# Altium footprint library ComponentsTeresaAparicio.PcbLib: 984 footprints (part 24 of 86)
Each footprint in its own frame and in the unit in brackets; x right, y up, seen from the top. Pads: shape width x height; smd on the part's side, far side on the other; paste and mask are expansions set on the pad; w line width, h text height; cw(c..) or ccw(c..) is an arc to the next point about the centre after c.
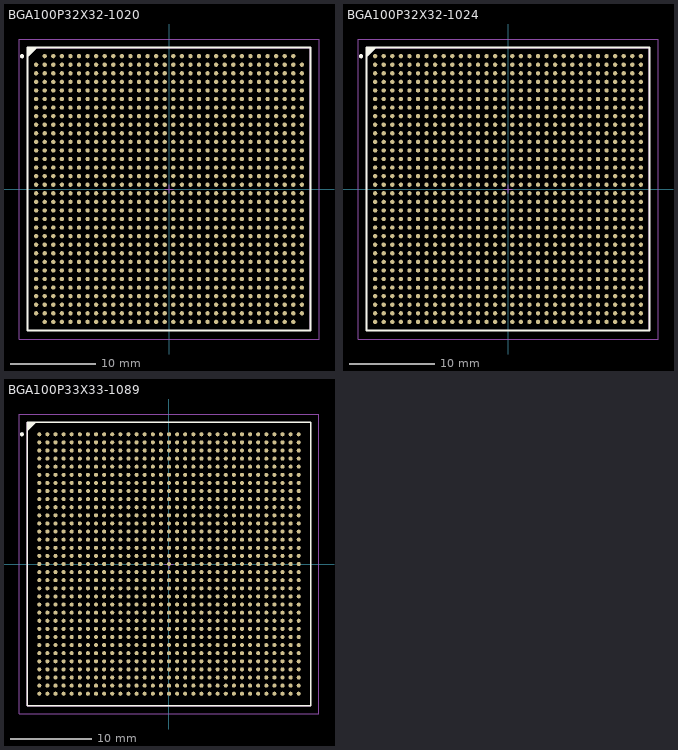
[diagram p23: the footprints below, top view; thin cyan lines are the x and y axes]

## BGA100P32X32-1020 [mm] "BGA, 1020-Leads, Body 33x33mm, Pitch 1mm"
height 3.5
pads (1020):
  round 0.5 smd: A2(-14.5,15.5) A3(-13.5,15.5) A4(-12.5,15.5) A5(-11.5,15.5) A6(-10.5,15.5) A7(-9.5,15.5) A8(-8.5,15.5) A9(-7.5,15.5) A10(-6.5,15.5) A11(-5.5,15.5) A12(-4.5,15.5) A13(-3.5,15.5) A14(-2.5,15.5) A15(-1.5,15.5) A16(-0.5,15.5) A17(0.5,15.5) A18(1.5,15.5) A19(2.5,15.5) A20(3.5,15.5) A21(4.5,15.5) A22(5.5,15.5) A23(6.5,15.5) A24(7.5,15.5) A25(8.5,15.5) A26(9.5,15.5) A27(10.5,15.5) A28(11.5,15.5) A29(12.5,15.5) A30(13.5,15.5) A31(14.5,15.5) AA1(-15.5,-4.5) AA2(-14.5,-4.5) AA3(-13.5,-4.5) AA4(-12.5,-4.5) AA5(-11.5,-4.5) AA6(-10.5,-4.5) AA7(-9.5,-4.5) AA8(-8.5,-4.5) AA9(-7.5,-4.5) AA10(-6.5,-4.5) AA11(-5.5,-4.5) AA12(-4.5,-4.5) AA13(-3.5,-4.5) AA14(-2.5,-4.5) AA15(-1.5,-4.5) AA16(-0.5,-4.5) AA17(0.5,-4.5) AA18(1.5,-4.5) AA19(2.5,-4.5) AA20(3.5,-4.5) AA21(4.5,-4.5) AA22(5.5,-4.5) AA23(6.5,-4.5) AA24(7.5,-4.5) AA25(8.5,-4.5) AA26(9.5,-4.5) AA27(10.5,-4.5) AA28(11.5,-4.5) AA29(12.5,-4.5) AA30(13.5,-4.5) AA31(14.5,-4.5) AA32(15.5,-4.5) AB1(-15.5,-5.5) AB2(-14.5,-5.5) AB3(-13.5,-5.5) AB4(-12.5,-5.5) AB5(-11.5,-5.5) AB6(-10.5,-5.5) AB7(-9.5,-5.5) AB8(-8.5,-5.5) AB9(-7.5,-5.5) AB10(-6.5,-5.5) AB11(-5.5,-5.5) AB12(-4.5,-5.5) AB13(-3.5,-5.5) AB14(-2.5,-5.5) AB15(-1.5,-5.5) AB16(-0.5,-5.5) AB17(0.5,-5.5) AB18(1.5,-5.5) AB19(2.5,-5.5) AB20(3.5,-5.5) AB21(4.5,-5.5) AB22(5.5,-5.5) AB23(6.5,-5.5) AB24(7.5,-5.5) AB25(8.5,-5.5) AB26(9.5,-5.5) AB27(10.5,-5.5) AB28(11.5,-5.5) AB29(12.5,-5.5) AB30(13.5,-5.5) AB31(14.5,-5.5) AB32(15.5,-5.5) AC1(-15.5,-6.5) AC2(-14.5,-6.5) AC3(-13.5,-6.5) AC4(-12.5,-6.5) AC5(-11.5,-6.5) AC6(-10.5,-6.5) AC7(-9.5,-6.5) AC8(-8.5,-6.5) AC9(-7.5,-6.5) AC10(-6.5,-6.5) AC11(-5.5,-6.5) AC12(-4.5,-6.5) AC13(-3.5,-6.5) AC14(-2.5,-6.5) AC15(-1.5,-6.5) AC16(-0.5,-6.5) AC17(0.5,-6.5) AC18(1.5,-6.5) AC19(2.5,-6.5) AC20(3.5,-6.5) AC21(4.5,-6.5) AC22(5.5,-6.5) AC23(6.5,-6.5) AC24(7.5,-6.5) AC25(8.5,-6.5) AC26(9.5,-6.5) AC27(10.5,-6.5) AC28(11.5,-6.5) AC29(12.5,-6.5) AC30(13.5,-6.5) AC31(14.5,-6.5) AC32(15.5,-6.5) AD1(-15.5,-7.5) AD2(-14.5,-7.5) AD3(-13.5,-7.5) AD4(-12.5,-7.5) AD5(-11.5,-7.5) AD6(-10.5,-7.5) AD7(-9.5,-7.5) AD8(-8.5,-7.5) AD9(-7.5,-7.5) AD10(-6.5,-7.5) AD11(-5.5,-7.5) AD12(-4.5,-7.5) AD13(-3.5,-7.5) AD14(-2.5,-7.5) AD15(-1.5,-7.5) AD16(-0.5,-7.5) AD17(0.5,-7.5) AD18(1.5,-7.5) AD19(2.5,-7.5) AD20(3.5,-7.5) AD21(4.5,-7.5) AD22(5.5,-7.5) AD23(6.5,-7.5) AD24(7.5,-7.5) AD25(8.5,-7.5) AD26(9.5,-7.5) AD27(10.5,-7.5) AD28(11.5,-7.5) AD29(12.5,-7.5) AD30(13.5,-7.5) AD31(14.5,-7.5) AD32(15.5,-7.5) AE1(-15.5,-8.5) AE2(-14.5,-8.5) AE3(-13.5,-8.5) AE4(-12.5,-8.5) AE5(-11.5,-8.5) AE6(-10.5,-8.5) AE7(-9.5,-8.5) AE8(-8.5,-8.5) AE9(-7.5,-8.5) AE10(-6.5,-8.5) AE11(-5.5,-8.5) AE12(-4.5,-8.5) AE13(-3.5,-8.5) AE14(-2.5,-8.5) AE15(-1.5,-8.5) AE16(-0.5,-8.5) AE17(0.5,-8.5) AE18(1.5,-8.5) AE19(2.5,-8.5) AE20(3.5,-8.5) AE21(4.5,-8.5) AE22(5.5,-8.5) AE23(6.5,-8.5) AE24(7.5,-8.5) AE25(8.5,-8.5) AE26(9.5,-8.5) AE27(10.5,-8.5) AE28(11.5,-8.5) AE29(12.5,-8.5) AE30(13.5,-8.5) AE31(14.5,-8.5) AE32(15.5,-8.5) AF1(-15.5,-9.5) AF2(-14.5,-9.5) AF3(-13.5,-9.5) AF4(-12.5,-9.5) AF5(-11.5,-9.5) AF6(-10.5,-9.5) AF7(-9.5,-9.5) AF8(-8.5,-9.5) AF9(-7.5,-9.5) AF10(-6.5,-9.5) AF11(-5.5,-9.5) AF12(-4.5,-9.5) AF13(-3.5,-9.5) AF14(-2.5,-9.5) AF15(-1.5,-9.5) AF16(-0.5,-9.5) AF17(0.5,-9.5) AF18(1.5,-9.5) AF19(2.5,-9.5) AF20(3.5,-9.5) AF21(4.5,-9.5) AF22(5.5,-9.5) AF23(6.5,-9.5) AF24(7.5,-9.5) AF25(8.5,-9.5) AF26(9.5,-9.5) AF27(10.5,-9.5) AF28(11.5,-9.5) AF29(12.5,-9.5) AF30(13.5,-9.5) AF31(14.5,-9.5) AF32(15.5,-9.5) AG1(-15.5,-10.5) AG2(-14.5,-10.5) AG3(-13.5,-10.5) AG4(-12.5,-10.5) AG5(-11.5,-10.5) AG6(-10.5,-10.5) AG7(-9.5,-10.5) AG8(-8.5,-10.5) AG9(-7.5,-10.5) AG10(-6.5,-10.5) AG11(-5.5,-10.5) AG12(-4.5,-10.5) AG13(-3.5,-10.5) AG14(-2.5,-10.5) AG15(-1.5,-10.5) AG16(-0.5,-10.5) AG17(0.5,-10.5) AG18(1.5,-10.5) AG19(2.5,-10.5) AG20(3.5,-10.5) AG21(4.5,-10.5) AG22(5.5,-10.5) AG23(6.5,-10.5) AG24(7.5,-10.5) AG25(8.5,-10.5) AG26(9.5,-10.5) AG27(10.5,-10.5) AG28(11.5,-10.5) AG29(12.5,-10.5) AG30(13.5,-10.5) AG31(14.5,-10.5) AG32(15.5,-10.5) AH1(-15.5,-11.5) AH2(-14.5,-11.5) AH3(-13.5,-11.5) AH4(-12.5,-11.5) AH5(-11.5,-11.5) AH6(-10.5,-11.5) AH7(-9.5,-11.5) AH8(-8.5,-11.5) AH9(-7.5,-11.5) AH10(-6.5,-11.5) AH11(-5.5,-11.5) AH12(-4.5,-11.5) AH13(-3.5,-11.5) AH14(-2.5,-11.5) AH15(-1.5,-11.5) AH16(-0.5,-11.5) AH17(0.5,-11.5) AH18(1.5,-11.5) AH19(2.5,-11.5) AH20(3.5,-11.5) AH21(4.5,-11.5) AH22(5.5,-11.5) AH23(6.5,-11.5) AH24(7.5,-11.5) AH25(8.5,-11.5) AH26(9.5,-11.5) AH27(10.5,-11.5) AH28(11.5,-11.5) AH29(12.5,-11.5) AH30(13.5,-11.5) AH31(14.5,-11.5) AH32(15.5,-11.5) AJ1(-15.5,-12.5) AJ2(-14.5,-12.5) AJ3(-13.5,-12.5) AJ4(-12.5,-12.5) AJ5(-11.5,-12.5) AJ6(-10.5,-12.5) AJ7(-9.5,-12.5) AJ8(-8.5,-12.5) AJ9(-7.5,-12.5) AJ10(-6.5,-12.5) AJ11(-5.5,-12.5) AJ12(-4.5,-12.5) AJ13(-3.5,-12.5) AJ14(-2.5,-12.5) AJ15(-1.5,-12.5) AJ16(-0.5,-12.5) AJ17(0.5,-12.5) AJ18(1.5,-12.5) AJ19(2.5,-12.5) AJ20(3.5,-12.5) AJ21(4.5,-12.5) AJ22(5.5,-12.5) AJ23(6.5,-12.5) AJ24(7.5,-12.5) AJ25(8.5,-12.5) AJ26(9.5,-12.5) AJ27(10.5,-12.5) AJ28(11.5,-12.5) AJ29(12.5,-12.5) AJ30(13.5,-12.5) AJ31(14.5,-12.5) AJ32(15.5,-12.5) AK1(-15.5,-13.5) AK2(-14.5,-13.5) AK3(-13.5,-13.5) AK4(-12.5,-13.5) AK5(-11.5,-13.5) AK6(-10.5,-13.5) AK7(-9.5,-13.5) AK8(-8.5,-13.5) AK9(-7.5,-13.5) AK10(-6.5,-13.5) AK11(-5.5,-13.5) AK12(-4.5,-13.5) AK13(-3.5,-13.5) AK14(-2.5,-13.5) AK15(-1.5,-13.5) AK16(-0.5,-13.5) AK17(0.5,-13.5) AK18(1.5,-13.5) AK19(2.5,-13.5) AK20(3.5,-13.5) AK21(4.5,-13.5) AK22(5.5,-13.5) AK23(6.5,-13.5) AK24(7.5,-13.5) AK25(8.5,-13.5) AK26(9.5,-13.5) AK27(10.5,-13.5) AK28(11.5,-13.5) AK29(12.5,-13.5) AK30(13.5,-13.5) AK31(14.5,-13.5) AK32(15.5,-13.5) AL1(-15.5,-14.5) AL2(-14.5,-14.5) AL3(-13.5,-14.5) AL4(-12.5,-14.5) AL5(-11.5,-14.5) AL6(-10.5,-14.5) AL7(-9.5,-14.5) AL8(-8.5,-14.5) AL9(-7.5,-14.5) AL10(-6.5,-14.5) AL11(-5.5,-14.5) AL12(-4.5,-14.5) AL13(-3.5,-14.5) AL14(-2.5,-14.5) AL15(-1.5,-14.5) AL16(-0.5,-14.5) AL17(0.5,-14.5) AL18(1.5,-14.5) AL19(2.5,-14.5) AL20(3.5,-14.5) AL21(4.5,-14.5) AL22(5.5,-14.5) AL23(6.5,-14.5) AL24(7.5,-14.5) AL25(8.5,-14.5) AL26(9.5,-14.5) AL27(10.5,-14.5) AL28(11.5,-14.5) AL29(12.5,-14.5) AL30(13.5,-14.5) AL31(14.5,-14.5) AL32(15.5,-14.5) AM2(-14.5,-15.5) AM3(-13.5,-15.5) AM4(-12.5,-15.5) AM5(-11.5,-15.5) AM6(-10.5,-15.5) AM7(-9.5,-15.5) AM8(-8.5,-15.5) AM9(-7.5,-15.5) AM10(-6.5,-15.5) AM11(-5.5,-15.5) AM12(-4.5,-15.5) AM13(-3.5,-15.5) AM14(-2.5,-15.5) AM15(-1.5,-15.5) AM16(-0.5,-15.5) AM17(0.5,-15.5) AM18(1.5,-15.5) AM19(2.5,-15.5) AM20(3.5,-15.5) AM21(4.5,-15.5) AM22(5.5,-15.5) AM23(6.5,-15.5) AM24(7.5,-15.5) AM25(8.5,-15.5) AM26(9.5,-15.5) AM27(10.5,-15.5) AM28(11.5,-15.5) AM29(12.5,-15.5) AM30(13.5,-15.5) AM31(14.5,-15.5) B1(-15.5,14.5) B2(-14.5,14.5) B3(-13.5,14.5) B4(-12.5,14.5) B5(-11.5,14.5) B6(-10.5,14.5) B7(-9.5,14.5) B8(-8.5,14.5) B9(-7.5,14.5) B10(-6.5,14.5) B11(-5.5,14.5) B12(-4.5,14.5) B13(-3.5,14.5) B14(-2.5,14.5) B15(-1.5,14.5) B16(-0.5,14.5) B17(0.5,14.5) B18(1.5,14.5) B19(2.5,14.5) B20(3.5,14.5) B21(4.5,14.5) B22(5.5,14.5) B23(6.5,14.5) B24(7.5,14.5) B25(8.5,14.5) B26(9.5,14.5) B27(10.5,14.5) B28(11.5,14.5) B29(12.5,14.5) B30(13.5,14.5) B31(14.5,14.5) B32(15.5,14.5) C1(-15.5,13.5) C2(-14.5,13.5) C3(-13.5,13.5) C4(-12.5,13.5) C5(-11.5,13.5) C6(-10.5,13.5) C7(-9.5,13.5) C8(-8.5,13.5) C9(-7.5,13.5) C10(-6.5,13.5) C11(-5.5,13.5) C12(-4.5,13.5) C13(-3.5,13.5) C14(-2.5,13.5) C15(-1.5,13.5) C16(-0.5,13.5) C17(0.5,13.5) C18(1.5,13.5) C19(2.5,13.5) C20(3.5,13.5) C21(4.5,13.5) C22(5.5,13.5) C23(6.5,13.5) C24(7.5,13.5) C25(8.5,13.5) C26(9.5,13.5) C27(10.5,13.5) C28(11.5,13.5) C29(12.5,13.5) C30(13.5,13.5) C31(14.5,13.5) C32(15.5,13.5) D1(-15.5,12.5) D2(-14.5,12.5) D3(-13.5,12.5) D4(-12.5,12.5) D5(-11.5,12.5) D6(-10.5,12.5) D7(-9.5,12.5) D8(-8.5,12.5) D9(-7.5,12.5) D10(-6.5,12.5) D11(-5.5,12.5) D12(-4.5,12.5) D13(-3.5,12.5) D14(-2.5,12.5) D15(-1.5,12.5) D16(-0.5,12.5) D17(0.5,12.5) D18(1.5,12.5) D19(2.5,12.5) D20(3.5,12.5) D21(4.5,12.5) D22(5.5,12.5) D23(6.5,12.5) D24(7.5,12.5) D25(8.5,12.5) D26(9.5,12.5) D27(10.5,12.5) D28(11.5,12.5) D29(12.5,12.5) D30(13.5,12.5) D31(14.5,12.5) D32(15.5,12.5) E1(-15.5,11.5) E2(-14.5,11.5) E3(-13.5,11.5) E4(-12.5,11.5) E5(-11.5,11.5) E6(-10.5,11.5) E7(-9.5,11.5) E8(-8.5,11.5) E9(-7.5,11.5) E10(-6.5,11.5) E11(-5.5,11.5) E12(-4.5,11.5) E13(-3.5,11.5) E14(-2.5,11.5) E15(-1.5,11.5) E16(-0.5,11.5) E17(0.5,11.5) E18(1.5,11.5) E19(2.5,11.5) E20(3.5,11.5) E21(4.5,11.5) E22(5.5,11.5) E23(6.5,11.5) E24(7.5,11.5) E25(8.5,11.5) E26(9.5,11.5) E27(10.5,11.5) E28(11.5,11.5) E29(12.5,11.5) E30(13.5,11.5) E31(14.5,11.5) E32(15.5,11.5) F1(-15.5,10.5) F2(-14.5,10.5) F3(-13.5,10.5) F4(-12.5,10.5) F5(-11.5,10.5) F6(-10.5,10.5) F7(-9.5,10.5) F8(-8.5,10.5) F9(-7.5,10.5) F10(-6.5,10.5) F11(-5.5,10.5) F12(-4.5,10.5) F13(-3.5,10.5) F14(-2.5,10.5) F15(-1.5,10.5) F16(-0.5,10.5) F17(0.5,10.5) F18(1.5,10.5) F19(2.5,10.5) F20(3.5,10.5) F21(4.5,10.5) F22(5.5,10.5) F23(6.5,10.5) F24(7.5,10.5) F25(8.5,10.5) F26(9.5,10.5) F27(10.5,10.5) F28(11.5,10.5) F29(12.5,10.5) F30(13.5,10.5) F31(14.5,10.5) F32(15.5,10.5) G1(-15.5,9.5) G2(-14.5,9.5) G3(-13.5,9.5) G4(-12.5,9.5) G5(-11.5,9.5) G6(-10.5,9.5) G7(-9.5,9.5) G8(-8.5,9.5) G9(-7.5,9.5) G10(-6.5,9.5) G11(-5.5,9.5) G12(-4.5,9.5) G13(-3.5,9.5) G14(-2.5,9.5) G15(-1.5,9.5) G16(-0.5,9.5) G17(0.5,9.5) G18(1.5,9.5) G19(2.5,9.5) G20(3.5,9.5) G21(4.5,9.5) G22(5.5,9.5) G23(6.5,9.5) G24(7.5,9.5) G25(8.5,9.5) G26(9.5,9.5) G27(10.5,9.5) G28(11.5,9.5) G29(12.5,9.5) G30(13.5,9.5) G31(14.5,9.5) G32(15.5,9.5) H1(-15.5,8.5) H2(-14.5,8.5) H3(-13.5,8.5) H4(-12.5,8.5) H5(-11.5,8.5) H6(-10.5,8.5) H7(-9.5,8.5) H8(-8.5,8.5) H9(-7.5,8.5) H10(-6.5,8.5) H11(-5.5,8.5) H12(-4.5,8.5) H13(-3.5,8.5) H14(-2.5,8.5) H15(-1.5,8.5) H16(-0.5,8.5) H17(0.5,8.5) H18(1.5,8.5) H19(2.5,8.5) H20(3.5,8.5) H21(4.5,8.5) H22(5.5,8.5) H23(6.5,8.5) H24(7.5,8.5) H25(8.5,8.5) H26(9.5,8.5) H27(10.5,8.5) H28(11.5,8.5) H29(12.5,8.5) H30(13.5,8.5) H31(14.5,8.5) H32(15.5,8.5) J1(-15.5,7.5) J2(-14.5,7.5) J3(-13.5,7.5) J4(-12.5,7.5) J5(-11.5,7.5) J6(-10.5,7.5) J7(-9.5,7.5) J8(-8.5,7.5) J9(-7.5,7.5) J10(-6.5,7.5) J11(-5.5,7.5) J12(-4.5,7.5) J13(-3.5,7.5) J14(-2.5,7.5) J15(-1.5,7.5) J16(-0.5,7.5) J17(0.5,7.5) J18(1.5,7.5) J19(2.5,7.5) J20(3.5,7.5) J21(4.5,7.5) J22(5.5,7.5) J23(6.5,7.5) J24(7.5,7.5) J25(8.5,7.5) J26(9.5,7.5) J27(10.5,7.5) J28(11.5,7.5) J29(12.5,7.5) J30(13.5,7.5) J31(14.5,7.5) J32(15.5,7.5) K1(-15.5,6.5) K2(-14.5,6.5) K3(-13.5,6.5) K4(-12.5,6.5) K5(-11.5,6.5) K6(-10.5,6.5) K7(-9.5,6.5) K8(-8.5,6.5) K9(-7.5,6.5) K10(-6.5,6.5) K11(-5.5,6.5) K12(-4.5,6.5) K13(-3.5,6.5) K14(-2.5,6.5) K15(-1.5,6.5) K16(-0.5,6.5) K17(0.5,6.5) K18(1.5,6.5) K19(2.5,6.5) K20(3.5,6.5) K21(4.5,6.5) K22(5.5,6.5) K23(6.5,6.5) K24(7.5,6.5) K25(8.5,6.5) K26(9.5,6.5) K27(10.5,6.5) K28(11.5,6.5) K29(12.5,6.5) K30(13.5,6.5) K31(14.5,6.5) K32(15.5,6.5) L1(-15.5,5.5) L2(-14.5,5.5) L3(-13.5,5.5) L4(-12.5,5.5) L5(-11.5,5.5) L6(-10.5,5.5) L7(-9.5,5.5) L8(-8.5,5.5) L9(-7.5,5.5) L10(-6.5,5.5) L11(-5.5,5.5) L12(-4.5,5.5) L13(-3.5,5.5) L14(-2.5,5.5) L15(-1.5,5.5) L16(-0.5,5.5) L17(0.5,5.5) L18(1.5,5.5) L19(2.5,5.5) L20(3.5,5.5) L21(4.5,5.5) L22(5.5,5.5) L23(6.5,5.5) L24(7.5,5.5) L25(8.5,5.5) L26(9.5,5.5) L27(10.5,5.5) L28(11.5,5.5) L29(12.5,5.5) L30(13.5,5.5) L31(14.5,5.5) L32(15.5,5.5) M1(-15.5,4.5) M2(-14.5,4.5) M3(-13.5,4.5) M4(-12.5,4.5) M5(-11.5,4.5) M6(-10.5,4.5) M7(-9.5,4.5) M8(-8.5,4.5) M9(-7.5,4.5) M10(-6.5,4.5) M11(-5.5,4.5) M12(-4.5,4.5) M13(-3.5,4.5) M14(-2.5,4.5) M15(-1.5,4.5) M16(-0.5,4.5) M17(0.5,4.5) M18(1.5,4.5) M19(2.5,4.5) M20(3.5,4.5) M21(4.5,4.5) M22(5.5,4.5) M23(6.5,4.5) M24(7.5,4.5) M25(8.5,4.5) M26(9.5,4.5) M27(10.5,4.5) M28(11.5,4.5) M29(12.5,4.5) M30(13.5,4.5) M31(14.5,4.5) M32(15.5,4.5) N1(-15.5,3.5) N2(-14.5,3.5) N3(-13.5,3.5) N4(-12.5,3.5) N5(-11.5,3.5) N6(-10.5,3.5) N7(-9.5,3.5) N8(-8.5,3.5) N9(-7.5,3.5) N10(-6.5,3.5) N11(-5.5,3.5) N12(-4.5,3.5) N13(-3.5,3.5) N14(-2.5,3.5) N15(-1.5,3.5) N16(-0.5,3.5) N17(0.5,3.5) N18(1.5,3.5) N19(2.5,3.5) N20(3.5,3.5) N21(4.5,3.5) N22(5.5,3.5) N23(6.5,3.5) N24(7.5,3.5) N25(8.5,3.5) N26(9.5,3.5) N27(10.5,3.5) N28(11.5,3.5) N29(12.5,3.5) N30(13.5,3.5) N31(14.5,3.5) N32(15.5,3.5) P1(-15.5,2.5) P2(-14.5,2.5) P3(-13.5,2.5) P4(-12.5,2.5) P5(-11.5,2.5) P6(-10.5,2.5) P7(-9.5,2.5) P8(-8.5,2.5) P9(-7.5,2.5) P10(-6.5,2.5) P11(-5.5,2.5) P12(-4.5,2.5) P13(-3.5,2.5) P14(-2.5,2.5) P15(-1.5,2.5) P16(-0.5,2.5) P17(0.5,2.5) P18(1.5,2.5) P19(2.5,2.5) P20(3.5,2.5) P21(4.5,2.5) P22(5.5,2.5) P23(6.5,2.5) P24(7.5,2.5) P25(8.5,2.5) P26(9.5,2.5) P27(10.5,2.5) P28(11.5,2.5) P29(12.5,2.5) P30(13.5,2.5) P31(14.5,2.5) P32(15.5,2.5) R1(-15.5,1.5) R2(-14.5,1.5) R3(-13.5,1.5) R4(-12.5,1.5) R5(-11.5,1.5) R6(-10.5,1.5) R7(-9.5,1.5) R8(-8.5,1.5) R9(-7.5,1.5) R10(-6.5,1.5) R11(-5.5,1.5) R12(-4.5,1.5) R13(-3.5,1.5) R14(-2.5,1.5) R15(-1.5,1.5) R16(-0.5,1.5) R17(0.5,1.5) R18(1.5,1.5) R19(2.5,1.5) R20(3.5,1.5) R21(4.5,1.5) R22(5.5,1.5) R23(6.5,1.5) R24(7.5,1.5) R25(8.5,1.5) R26(9.5,1.5) R27(10.5,1.5) R28(11.5,1.5) R29(12.5,1.5) R30(13.5,1.5) R31(14.5,1.5) R32(15.5,1.5) T1(-15.5,0.5) T2(-14.5,0.5) T3(-13.5,0.5) T4(-12.5,0.5) T5(-11.5,0.5) T6(-10.5,0.5) T7(-9.5,0.5) T8(-8.5,0.5) T9(-7.5,0.5) T10(-6.5,0.5) T11(-5.5,0.5) T12(-4.5,0.5) T13(-3.5,0.5) T14(-2.5,0.5) T15(-1.5,0.5) T16(-0.5,0.5) T17(0.5,0.5) T18(1.5,0.5) T19(2.5,0.5) T20(3.5,0.5) T21(4.5,0.5) T22(5.5,0.5) T23(6.5,0.5) T24(7.5,0.5) T25(8.5,0.5) T26(9.5,0.5) T27(10.5,0.5) T28(11.5,0.5) T29(12.5,0.5) T30(13.5,0.5) T31(14.5,0.5) T32(15.5,0.5) U1(-15.5,-0.5) U2(-14.5,-0.5) U3(-13.5,-0.5) U4(-12.5,-0.5) U5(-11.5,-0.5) U6(-10.5,-0.5) U7(-9.5,-0.5) U8(-8.5,-0.5) U9(-7.5,-0.5) U10(-6.5,-0.5) U11(-5.5,-0.5) U12(-4.5,-0.5) U13(-3.5,-0.5) U14(-2.5,-0.5) U15(-1.5,-0.5) U16(-0.5,-0.5) U17(0.5,-0.5) U18(1.5,-0.5) U19(2.5,-0.5) U20(3.5,-0.5) U21(4.5,-0.5) U22(5.5,-0.5) U23(6.5,-0.5) U24(7.5,-0.5) U25(8.5,-0.5) U26(9.5,-0.5) U27(10.5,-0.5) U28(11.5,-0.5) U29(12.5,-0.5) U30(13.5,-0.5) U31(14.5,-0.5) U32(15.5,-0.5) V1(-15.5,-1.5) V2(-14.5,-1.5) V3(-13.5,-1.5) V4(-12.5,-1.5) V5(-11.5,-1.5) V6(-10.5,-1.5) V7(-9.5,-1.5) V8(-8.5,-1.5) V9(-7.5,-1.5) V10(-6.5,-1.5) V11(-5.5,-1.5) V12(-4.5,-1.5) V13(-3.5,-1.5) V14(-2.5,-1.5) V15(-1.5,-1.5) V16(-0.5,-1.5) V17(0.5,-1.5) V18(1.5,-1.5) V19(2.5,-1.5) V20(3.5,-1.5) V21(4.5,-1.5) V22(5.5,-1.5) V23(6.5,-1.5) V24(7.5,-1.5) V25(8.5,-1.5) V26(9.5,-1.5) V27(10.5,-1.5) V28(11.5,-1.5) V29(12.5,-1.5) V30(13.5,-1.5) V31(14.5,-1.5) V32(15.5,-1.5) W1(-15.5,-2.5) W2(-14.5,-2.5) W3(-13.5,-2.5) W4(-12.5,-2.5) W5(-11.5,-2.5) W6(-10.5,-2.5) W7(-9.5,-2.5) W8(-8.5,-2.5) W9(-7.5,-2.5) W10(-6.5,-2.5) W11(-5.5,-2.5) W12(-4.5,-2.5) W13(-3.5,-2.5) W14(-2.5,-2.5) W15(-1.5,-2.5) W16(-0.5,-2.5) W17(0.5,-2.5) W18(1.5,-2.5) W19(2.5,-2.5) W20(3.5,-2.5) W21(4.5,-2.5) W22(5.5,-2.5) W23(6.5,-2.5) W24(7.5,-2.5) W25(8.5,-2.5) W26(9.5,-2.5) W27(10.5,-2.5) W28(11.5,-2.5) W29(12.5,-2.5) W30(13.5,-2.5) W31(14.5,-2.5) W32(15.5,-2.5) Y1(-15.5,-3.5) Y2(-14.5,-3.5) Y3(-13.5,-3.5) Y4(-12.5,-3.5) Y5(-11.5,-3.5) Y6(-10.5,-3.5) Y7(-9.5,-3.5) Y8(-8.5,-3.5) Y9(-7.5,-3.5) Y10(-6.5,-3.5) Y11(-5.5,-3.5) Y12(-4.5,-3.5) Y13(-3.5,-3.5) Y14(-2.5,-3.5) Y15(-1.5,-3.5) Y16(-0.5,-3.5) Y17(0.5,-3.5) Y18(1.5,-3.5) Y19(2.5,-3.5) Y20(3.5,-3.5) Y21(4.5,-3.5) Y22(5.5,-3.5) Y23(6.5,-3.5) Y24(7.5,-3.5) Y25(8.5,-3.5) Y26(9.5,-3.5) Y27(10.5,-3.5) Y28(11.5,-3.5) Y29(12.5,-3.5) Y30(13.5,-3.5) Y31(14.5,-3.5) Y32(15.5,-3.5)
Top Overlay:
  circle w0.25: c-17.15,15.5 r0.125
  region: -15.5,16.5 -16.5,15.5 -16.5,16.5
  lines w0.2: -16.5,15.5 -15.5,16.5 ; -16.5,-16.5 -16.5,16.5 16.5,16.5 16.5,-16.5 -16.5,-16.5
Mechanical 13:
  lines w0.1: -16.5,-16.5 -16.5,16.5 16.5,16.5 16.5,-16.5 -16.5,-16.5
Mechanical 15:
  lines w0.1: -0.5,0 0.5,0 ; 0,-0.5 0,0.5 ; -17.5,-17.5 -17.5,17.5 17.5,17.5 17.5,-17.5 -17.5,-17.5
3D body: height 0, standoff 0, extent -16.5,-16.5 16.5,16.5

## BGA100P32X32-1024 [mm] "BGA, 1024-Leads, Body 33x33mm, Pitch 1mm"
height 3.5
pads (1024):
  round 0.5 smd: A1(-15.5,15.5) A2(-14.5,15.5) A3(-13.5,15.5) A4(-12.5,15.5) A5(-11.5,15.5) A6(-10.5,15.5) A7(-9.5,15.5) A8(-8.5,15.5) A9(-7.5,15.5) A10(-6.5,15.5) A11(-5.5,15.5) A12(-4.5,15.5) A13(-3.5,15.5) A14(-2.5,15.5) A15(-1.5,15.5) A16(-0.5,15.5) A17(0.5,15.5) A18(1.5,15.5) A19(2.5,15.5) A20(3.5,15.5) A21(4.5,15.5) A22(5.5,15.5) A23(6.5,15.5) A24(7.5,15.5) A25(8.5,15.5) A26(9.5,15.5) A27(10.5,15.5) A28(11.5,15.5) A29(12.5,15.5) A30(13.5,15.5) A31(14.5,15.5) A32(15.5,15.5) AA1(-15.5,-4.5) AA2(-14.5,-4.5) AA3(-13.5,-4.5) AA4(-12.5,-4.5) AA5(-11.5,-4.5) AA6(-10.5,-4.5) AA7(-9.5,-4.5) AA8(-8.5,-4.5) AA9(-7.5,-4.5) AA10(-6.5,-4.5) AA11(-5.5,-4.5) AA12(-4.5,-4.5) AA13(-3.5,-4.5) AA14(-2.5,-4.5) AA15(-1.5,-4.5) AA16(-0.5,-4.5) AA17(0.5,-4.5) AA18(1.5,-4.5) AA19(2.5,-4.5) AA20(3.5,-4.5) AA21(4.5,-4.5) AA22(5.5,-4.5) AA23(6.5,-4.5) AA24(7.5,-4.5) AA25(8.5,-4.5) AA26(9.5,-4.5) AA27(10.5,-4.5) AA28(11.5,-4.5) AA29(12.5,-4.5) AA30(13.5,-4.5) AA31(14.5,-4.5) AA32(15.5,-4.5) AB1(-15.5,-5.5) AB2(-14.5,-5.5) AB3(-13.5,-5.5) AB4(-12.5,-5.5) AB5(-11.5,-5.5) AB6(-10.5,-5.5) AB7(-9.5,-5.5) AB8(-8.5,-5.5) AB9(-7.5,-5.5) AB10(-6.5,-5.5) AB11(-5.5,-5.5) AB12(-4.5,-5.5) AB13(-3.5,-5.5) AB14(-2.5,-5.5) AB15(-1.5,-5.5) AB16(-0.5,-5.5) AB17(0.5,-5.5) AB18(1.5,-5.5) AB19(2.5,-5.5) AB20(3.5,-5.5) AB21(4.5,-5.5) AB22(5.5,-5.5) AB23(6.5,-5.5) AB24(7.5,-5.5) AB25(8.5,-5.5) AB26(9.5,-5.5) AB27(10.5,-5.5) AB28(11.5,-5.5) AB29(12.5,-5.5) AB30(13.5,-5.5) AB31(14.5,-5.5) AB32(15.5,-5.5) AC1(-15.5,-6.5) AC2(-14.5,-6.5) AC3(-13.5,-6.5) AC4(-12.5,-6.5) AC5(-11.5,-6.5) AC6(-10.5,-6.5) AC7(-9.5,-6.5) AC8(-8.5,-6.5) AC9(-7.5,-6.5) AC10(-6.5,-6.5) AC11(-5.5,-6.5) AC12(-4.5,-6.5) AC13(-3.5,-6.5) AC14(-2.5,-6.5) AC15(-1.5,-6.5) AC16(-0.5,-6.5) AC17(0.5,-6.5) AC18(1.5,-6.5) AC19(2.5,-6.5) AC20(3.5,-6.5) AC21(4.5,-6.5) AC22(5.5,-6.5) AC23(6.5,-6.5) AC24(7.5,-6.5) AC25(8.5,-6.5) AC26(9.5,-6.5) AC27(10.5,-6.5) AC28(11.5,-6.5) AC29(12.5,-6.5) AC30(13.5,-6.5) AC31(14.5,-6.5) AC32(15.5,-6.5) AD1(-15.5,-7.5) AD2(-14.5,-7.5) AD3(-13.5,-7.5) AD4(-12.5,-7.5) AD5(-11.5,-7.5) AD6(-10.5,-7.5) AD7(-9.5,-7.5) AD8(-8.5,-7.5) AD9(-7.5,-7.5) AD10(-6.5,-7.5) AD11(-5.5,-7.5) AD12(-4.5,-7.5) AD13(-3.5,-7.5) AD14(-2.5,-7.5) AD15(-1.5,-7.5) AD16(-0.5,-7.5) AD17(0.5,-7.5) AD18(1.5,-7.5) AD19(2.5,-7.5) AD20(3.5,-7.5) AD21(4.5,-7.5) AD22(5.5,-7.5) AD23(6.5,-7.5) AD24(7.5,-7.5) AD25(8.5,-7.5) AD26(9.5,-7.5) AD27(10.5,-7.5) AD28(11.5,-7.5) AD29(12.5,-7.5) AD30(13.5,-7.5) AD31(14.5,-7.5) AD32(15.5,-7.5) AE1(-15.5,-8.5) AE2(-14.5,-8.5) AE3(-13.5,-8.5) AE4(-12.5,-8.5) AE5(-11.5,-8.5) AE6(-10.5,-8.5) AE7(-9.5,-8.5) AE8(-8.5,-8.5) AE9(-7.5,-8.5) AE10(-6.5,-8.5) AE11(-5.5,-8.5) AE12(-4.5,-8.5) AE13(-3.5,-8.5) AE14(-2.5,-8.5) AE15(-1.5,-8.5) AE16(-0.5,-8.5) AE17(0.5,-8.5) AE18(1.5,-8.5) AE19(2.5,-8.5) AE20(3.5,-8.5) AE21(4.5,-8.5) AE22(5.5,-8.5) AE23(6.5,-8.5) AE24(7.5,-8.5) AE25(8.5,-8.5) AE26(9.5,-8.5) AE27(10.5,-8.5) AE28(11.5,-8.5) AE29(12.5,-8.5) AE30(13.5,-8.5) AE31(14.5,-8.5) AE32(15.5,-8.5) AF1(-15.5,-9.5) AF2(-14.5,-9.5) AF3(-13.5,-9.5) AF4(-12.5,-9.5) AF5(-11.5,-9.5) AF6(-10.5,-9.5) AF7(-9.5,-9.5) AF8(-8.5,-9.5) AF9(-7.5,-9.5) AF10(-6.5,-9.5) AF11(-5.5,-9.5) AF12(-4.5,-9.5) AF13(-3.5,-9.5) AF14(-2.5,-9.5) AF15(-1.5,-9.5) AF16(-0.5,-9.5) AF17(0.5,-9.5) AF18(1.5,-9.5) AF19(2.5,-9.5) AF20(3.5,-9.5) AF21(4.5,-9.5) AF22(5.5,-9.5) AF23(6.5,-9.5) AF24(7.5,-9.5) AF25(8.5,-9.5) AF26(9.5,-9.5) AF27(10.5,-9.5) AF28(11.5,-9.5) AF29(12.5,-9.5) AF30(13.5,-9.5) AF31(14.5,-9.5) AF32(15.5,-9.5) AG1(-15.5,-10.5) AG2(-14.5,-10.5) AG3(-13.5,-10.5) AG4(-12.5,-10.5) AG5(-11.5,-10.5) AG6(-10.5,-10.5) AG7(-9.5,-10.5) AG8(-8.5,-10.5) AG9(-7.5,-10.5) AG10(-6.5,-10.5) AG11(-5.5,-10.5) AG12(-4.5,-10.5) AG13(-3.5,-10.5) AG14(-2.5,-10.5) AG15(-1.5,-10.5) AG16(-0.5,-10.5) AG17(0.5,-10.5) AG18(1.5,-10.5) AG19(2.5,-10.5) AG20(3.5,-10.5) AG21(4.5,-10.5) AG22(5.5,-10.5) AG23(6.5,-10.5) AG24(7.5,-10.5) AG25(8.5,-10.5) AG26(9.5,-10.5) AG27(10.5,-10.5) AG28(11.5,-10.5) AG29(12.5,-10.5) AG30(13.5,-10.5) AG31(14.5,-10.5) AG32(15.5,-10.5) AH1(-15.5,-11.5) AH2(-14.5,-11.5) AH3(-13.5,-11.5) AH4(-12.5,-11.5) AH5(-11.5,-11.5) AH6(-10.5,-11.5) AH7(-9.5,-11.5) AH8(-8.5,-11.5) AH9(-7.5,-11.5) AH10(-6.5,-11.5) AH11(-5.5,-11.5) AH12(-4.5,-11.5) AH13(-3.5,-11.5) AH14(-2.5,-11.5) AH15(-1.5,-11.5) AH16(-0.5,-11.5) AH17(0.5,-11.5) AH18(1.5,-11.5) AH19(2.5,-11.5) AH20(3.5,-11.5) AH21(4.5,-11.5) AH22(5.5,-11.5) AH23(6.5,-11.5) AH24(7.5,-11.5) AH25(8.5,-11.5) AH26(9.5,-11.5) AH27(10.5,-11.5) AH28(11.5,-11.5) AH29(12.5,-11.5) AH30(13.5,-11.5) AH31(14.5,-11.5) AH32(15.5,-11.5) AJ1(-15.5,-12.5) AJ2(-14.5,-12.5) AJ3(-13.5,-12.5) AJ4(-12.5,-12.5) AJ5(-11.5,-12.5) AJ6(-10.5,-12.5) AJ7(-9.5,-12.5) AJ8(-8.5,-12.5) AJ9(-7.5,-12.5) AJ10(-6.5,-12.5) AJ11(-5.5,-12.5) AJ12(-4.5,-12.5) AJ13(-3.5,-12.5) AJ14(-2.5,-12.5) AJ15(-1.5,-12.5) AJ16(-0.5,-12.5) AJ17(0.5,-12.5) AJ18(1.5,-12.5) AJ19(2.5,-12.5) AJ20(3.5,-12.5) AJ21(4.5,-12.5) AJ22(5.5,-12.5) AJ23(6.5,-12.5) AJ24(7.5,-12.5) AJ25(8.5,-12.5) AJ26(9.5,-12.5) AJ27(10.5,-12.5) AJ28(11.5,-12.5) AJ29(12.5,-12.5) AJ30(13.5,-12.5) AJ31(14.5,-12.5) AJ32(15.5,-12.5) AK1(-15.5,-13.5) AK2(-14.5,-13.5) AK3(-13.5,-13.5) AK4(-12.5,-13.5) AK5(-11.5,-13.5) AK6(-10.5,-13.5) AK7(-9.5,-13.5) AK8(-8.5,-13.5) AK9(-7.5,-13.5) AK10(-6.5,-13.5) AK11(-5.5,-13.5) AK12(-4.5,-13.5) AK13(-3.5,-13.5) AK14(-2.5,-13.5) AK15(-1.5,-13.5) AK16(-0.5,-13.5) AK17(0.5,-13.5) AK18(1.5,-13.5) AK19(2.5,-13.5) AK20(3.5,-13.5) AK21(4.5,-13.5) AK22(5.5,-13.5) AK23(6.5,-13.5) AK24(7.5,-13.5) AK25(8.5,-13.5) AK26(9.5,-13.5) AK27(10.5,-13.5) AK28(11.5,-13.5) AK29(12.5,-13.5) AK30(13.5,-13.5) AK31(14.5,-13.5) AK32(15.5,-13.5) AL1(-15.5,-14.5) AL2(-14.5,-14.5) AL3(-13.5,-14.5) AL4(-12.5,-14.5) AL5(-11.5,-14.5) AL6(-10.5,-14.5) AL7(-9.5,-14.5) AL8(-8.5,-14.5) AL9(-7.5,-14.5) AL10(-6.5,-14.5) AL11(-5.5,-14.5) AL12(-4.5,-14.5) AL13(-3.5,-14.5) AL14(-2.5,-14.5) AL15(-1.5,-14.5) AL16(-0.5,-14.5) AL17(0.5,-14.5) AL18(1.5,-14.5) AL19(2.5,-14.5) AL20(3.5,-14.5) AL21(4.5,-14.5) AL22(5.5,-14.5) AL23(6.5,-14.5) AL24(7.5,-14.5) AL25(8.5,-14.5) AL26(9.5,-14.5) AL27(10.5,-14.5) AL28(11.5,-14.5) AL29(12.5,-14.5) AL30(13.5,-14.5) AL31(14.5,-14.5) AL32(15.5,-14.5) AM1(-15.5,-15.5) AM2(-14.5,-15.5) AM3(-13.5,-15.5) AM4(-12.5,-15.5) AM5(-11.5,-15.5) AM6(-10.5,-15.5) AM7(-9.5,-15.5) AM8(-8.5,-15.5) AM9(-7.5,-15.5) AM10(-6.5,-15.5) AM11(-5.5,-15.5) AM12(-4.5,-15.5) AM13(-3.5,-15.5) AM14(-2.5,-15.5) AM15(-1.5,-15.5) AM16(-0.5,-15.5) AM17(0.5,-15.5) AM18(1.5,-15.5) AM19(2.5,-15.5) AM20(3.5,-15.5) AM21(4.5,-15.5) AM22(5.5,-15.5) AM23(6.5,-15.5) AM24(7.5,-15.5) AM25(8.5,-15.5) AM26(9.5,-15.5) AM27(10.5,-15.5) AM28(11.5,-15.5) AM29(12.5,-15.5) AM30(13.5,-15.5) AM31(14.5,-15.5) AM32(15.5,-15.5) B1(-15.5,14.5) B2(-14.5,14.5) B3(-13.5,14.5) B4(-12.5,14.5) B5(-11.5,14.5) B6(-10.5,14.5) B7(-9.5,14.5) B8(-8.5,14.5) B9(-7.5,14.5) B10(-6.5,14.5) B11(-5.5,14.5) B12(-4.5,14.5) B13(-3.5,14.5) B14(-2.5,14.5) B15(-1.5,14.5) B16(-0.5,14.5) B17(0.5,14.5) B18(1.5,14.5) B19(2.5,14.5) B20(3.5,14.5) B21(4.5,14.5) B22(5.5,14.5) B23(6.5,14.5) B24(7.5,14.5) B25(8.5,14.5) B26(9.5,14.5) B27(10.5,14.5) B28(11.5,14.5) B29(12.5,14.5) B30(13.5,14.5) B31(14.5,14.5) B32(15.5,14.5) C1(-15.5,13.5) C2(-14.5,13.5) C3(-13.5,13.5) C4(-12.5,13.5) C5(-11.5,13.5) C6(-10.5,13.5) C7(-9.5,13.5) C8(-8.5,13.5) C9(-7.5,13.5) C10(-6.5,13.5) C11(-5.5,13.5) C12(-4.5,13.5) C13(-3.5,13.5) C14(-2.5,13.5) C15(-1.5,13.5) C16(-0.5,13.5) C17(0.5,13.5) C18(1.5,13.5) C19(2.5,13.5) C20(3.5,13.5) C21(4.5,13.5) C22(5.5,13.5) C23(6.5,13.5) C24(7.5,13.5) C25(8.5,13.5) C26(9.5,13.5) C27(10.5,13.5) C28(11.5,13.5) C29(12.5,13.5) C30(13.5,13.5) C31(14.5,13.5) C32(15.5,13.5) D1(-15.5,12.5) D2(-14.5,12.5) D3(-13.5,12.5) D4(-12.5,12.5) D5(-11.5,12.5) D6(-10.5,12.5) D7(-9.5,12.5) D8(-8.5,12.5) D9(-7.5,12.5) D10(-6.5,12.5) D11(-5.5,12.5) D12(-4.5,12.5) D13(-3.5,12.5) D14(-2.5,12.5) D15(-1.5,12.5) D16(-0.5,12.5) D17(0.5,12.5) D18(1.5,12.5) D19(2.5,12.5) D20(3.5,12.5) D21(4.5,12.5) D22(5.5,12.5) D23(6.5,12.5) D24(7.5,12.5) D25(8.5,12.5) D26(9.5,12.5) D27(10.5,12.5) D28(11.5,12.5) D29(12.5,12.5) D30(13.5,12.5) D31(14.5,12.5) D32(15.5,12.5) E1(-15.5,11.5) E2(-14.5,11.5) E3(-13.5,11.5) E4(-12.5,11.5) E5(-11.5,11.5) E6(-10.5,11.5) E7(-9.5,11.5) E8(-8.5,11.5) E9(-7.5,11.5) E10(-6.5,11.5) E11(-5.5,11.5) E12(-4.5,11.5) E13(-3.5,11.5) E14(-2.5,11.5) E15(-1.5,11.5) E16(-0.5,11.5) E17(0.5,11.5) E18(1.5,11.5) E19(2.5,11.5) E20(3.5,11.5) E21(4.5,11.5) E22(5.5,11.5) E23(6.5,11.5) E24(7.5,11.5) E25(8.5,11.5) E26(9.5,11.5) E27(10.5,11.5) E28(11.5,11.5) E29(12.5,11.5) E30(13.5,11.5) E31(14.5,11.5) E32(15.5,11.5) F1(-15.5,10.5) F2(-14.5,10.5) F3(-13.5,10.5) F4(-12.5,10.5) F5(-11.5,10.5) F6(-10.5,10.5) F7(-9.5,10.5) F8(-8.5,10.5) F9(-7.5,10.5) F10(-6.5,10.5) F11(-5.5,10.5) F12(-4.5,10.5) F13(-3.5,10.5) F14(-2.5,10.5) F15(-1.5,10.5) F16(-0.5,10.5) F17(0.5,10.5) F18(1.5,10.5) F19(2.5,10.5) F20(3.5,10.5) F21(4.5,10.5) F22(5.5,10.5) F23(6.5,10.5) F24(7.5,10.5) F25(8.5,10.5) F26(9.5,10.5) F27(10.5,10.5) F28(11.5,10.5) F29(12.5,10.5) F30(13.5,10.5) F31(14.5,10.5) F32(15.5,10.5) G1(-15.5,9.5) G2(-14.5,9.5) G3(-13.5,9.5) G4(-12.5,9.5) G5(-11.5,9.5) G6(-10.5,9.5) G7(-9.5,9.5) G8(-8.5,9.5) G9(-7.5,9.5) G10(-6.5,9.5) G11(-5.5,9.5) G12(-4.5,9.5) G13(-3.5,9.5) G14(-2.5,9.5) G15(-1.5,9.5) G16(-0.5,9.5) G17(0.5,9.5) G18(1.5,9.5) G19(2.5,9.5) G20(3.5,9.5) G21(4.5,9.5) G22(5.5,9.5) G23(6.5,9.5) G24(7.5,9.5) G25(8.5,9.5) G26(9.5,9.5) G27(10.5,9.5) G28(11.5,9.5) G29(12.5,9.5) G30(13.5,9.5) G31(14.5,9.5) G32(15.5,9.5) H1(-15.5,8.5) H2(-14.5,8.5) H3(-13.5,8.5) H4(-12.5,8.5) H5(-11.5,8.5) H6(-10.5,8.5) H7(-9.5,8.5) H8(-8.5,8.5) H9(-7.5,8.5) H10(-6.5,8.5) H11(-5.5,8.5) H12(-4.5,8.5) H13(-3.5,8.5) H14(-2.5,8.5) H15(-1.5,8.5) H16(-0.5,8.5) H17(0.5,8.5) H18(1.5,8.5) H19(2.5,8.5) H20(3.5,8.5) H21(4.5,8.5) H22(5.5,8.5) H23(6.5,8.5) H24(7.5,8.5) H25(8.5,8.5) H26(9.5,8.5) H27(10.5,8.5) H28(11.5,8.5) H29(12.5,8.5) H30(13.5,8.5) H31(14.5,8.5) H32(15.5,8.5) J1(-15.5,7.5) J2(-14.5,7.5) J3(-13.5,7.5) J4(-12.5,7.5) J5(-11.5,7.5) J6(-10.5,7.5) J7(-9.5,7.5) J8(-8.5,7.5) J9(-7.5,7.5) J10(-6.5,7.5) J11(-5.5,7.5) J12(-4.5,7.5) J13(-3.5,7.5) J14(-2.5,7.5) J15(-1.5,7.5) J16(-0.5,7.5) J17(0.5,7.5) J18(1.5,7.5) J19(2.5,7.5) J20(3.5,7.5) J21(4.5,7.5) J22(5.5,7.5) J23(6.5,7.5) J24(7.5,7.5) J25(8.5,7.5) J26(9.5,7.5) J27(10.5,7.5) J28(11.5,7.5) J29(12.5,7.5) J30(13.5,7.5) J31(14.5,7.5) J32(15.5,7.5) K1(-15.5,6.5) K2(-14.5,6.5) K3(-13.5,6.5) K4(-12.5,6.5) K5(-11.5,6.5) K6(-10.5,6.5) K7(-9.5,6.5) K8(-8.5,6.5) K9(-7.5,6.5) K10(-6.5,6.5) K11(-5.5,6.5) K12(-4.5,6.5) K13(-3.5,6.5) K14(-2.5,6.5) K15(-1.5,6.5) K16(-0.5,6.5) K17(0.5,6.5) K18(1.5,6.5) K19(2.5,6.5) K20(3.5,6.5) K21(4.5,6.5) K22(5.5,6.5) K23(6.5,6.5) K24(7.5,6.5) K25(8.5,6.5) K26(9.5,6.5) K27(10.5,6.5) K28(11.5,6.5) K29(12.5,6.5) K30(13.5,6.5) K31(14.5,6.5) K32(15.5,6.5) L1(-15.5,5.5) L2(-14.5,5.5) L3(-13.5,5.5) L4(-12.5,5.5) L5(-11.5,5.5) L6(-10.5,5.5) L7(-9.5,5.5) L8(-8.5,5.5) L9(-7.5,5.5) L10(-6.5,5.5) L11(-5.5,5.5) L12(-4.5,5.5) L13(-3.5,5.5) L14(-2.5,5.5) L15(-1.5,5.5) L16(-0.5,5.5) L17(0.5,5.5) L18(1.5,5.5) L19(2.5,5.5) L20(3.5,5.5) L21(4.5,5.5) L22(5.5,5.5) L23(6.5,5.5) L24(7.5,5.5) L25(8.5,5.5) L26(9.5,5.5) L27(10.5,5.5) L28(11.5,5.5) L29(12.5,5.5) L30(13.5,5.5) L31(14.5,5.5) L32(15.5,5.5) M1(-15.5,4.5) M2(-14.5,4.5) M3(-13.5,4.5) M4(-12.5,4.5) M5(-11.5,4.5) M6(-10.5,4.5) M7(-9.5,4.5) M8(-8.5,4.5) M9(-7.5,4.5) M10(-6.5,4.5) M11(-5.5,4.5) M12(-4.5,4.5) M13(-3.5,4.5) M14(-2.5,4.5) M15(-1.5,4.5) M16(-0.5,4.5) M17(0.5,4.5) M18(1.5,4.5) M19(2.5,4.5) M20(3.5,4.5) M21(4.5,4.5) M22(5.5,4.5) M23(6.5,4.5) M24(7.5,4.5) M25(8.5,4.5) M26(9.5,4.5) M27(10.5,4.5) M28(11.5,4.5) M29(12.5,4.5) M30(13.5,4.5) M31(14.5,4.5) M32(15.5,4.5) N1(-15.5,3.5) N2(-14.5,3.5) N3(-13.5,3.5) N4(-12.5,3.5) N5(-11.5,3.5) N6(-10.5,3.5) N7(-9.5,3.5) N8(-8.5,3.5) N9(-7.5,3.5) N10(-6.5,3.5) N11(-5.5,3.5) N12(-4.5,3.5) N13(-3.5,3.5) N14(-2.5,3.5) N15(-1.5,3.5) N16(-0.5,3.5) N17(0.5,3.5) N18(1.5,3.5) N19(2.5,3.5) N20(3.5,3.5) N21(4.5,3.5) N22(5.5,3.5) N23(6.5,3.5) N24(7.5,3.5) N25(8.5,3.5) N26(9.5,3.5) N27(10.5,3.5) N28(11.5,3.5) N29(12.5,3.5) N30(13.5,3.5) N31(14.5,3.5) N32(15.5,3.5) P1(-15.5,2.5) P2(-14.5,2.5) P3(-13.5,2.5) P4(-12.5,2.5) P5(-11.5,2.5) P6(-10.5,2.5) P7(-9.5,2.5) P8(-8.5,2.5) P9(-7.5,2.5) P10(-6.5,2.5) P11(-5.5,2.5) P12(-4.5,2.5) P13(-3.5,2.5) P14(-2.5,2.5) P15(-1.5,2.5) P16(-0.5,2.5) P17(0.5,2.5) P18(1.5,2.5) P19(2.5,2.5) P20(3.5,2.5) P21(4.5,2.5) P22(5.5,2.5) P23(6.5,2.5) P24(7.5,2.5) P25(8.5,2.5) P26(9.5,2.5) P27(10.5,2.5) P28(11.5,2.5) P29(12.5,2.5) P30(13.5,2.5) P31(14.5,2.5) P32(15.5,2.5) R1(-15.5,1.5) R2(-14.5,1.5) R3(-13.5,1.5) R4(-12.5,1.5) R5(-11.5,1.5) R6(-10.5,1.5) R7(-9.5,1.5) R8(-8.5,1.5) R9(-7.5,1.5) R10(-6.5,1.5) R11(-5.5,1.5) R12(-4.5,1.5) R13(-3.5,1.5) R14(-2.5,1.5) R15(-1.5,1.5) R16(-0.5,1.5) R17(0.5,1.5) R18(1.5,1.5) R19(2.5,1.5) R20(3.5,1.5) R21(4.5,1.5) R22(5.5,1.5) R23(6.5,1.5) R24(7.5,1.5) R25(8.5,1.5) R26(9.5,1.5) R27(10.5,1.5) R28(11.5,1.5) R29(12.5,1.5) R30(13.5,1.5) R31(14.5,1.5) R32(15.5,1.5) T1(-15.5,0.5) T2(-14.5,0.5) T3(-13.5,0.5) T4(-12.5,0.5) T5(-11.5,0.5) T6(-10.5,0.5) T7(-9.5,0.5) T8(-8.5,0.5) T9(-7.5,0.5) T10(-6.5,0.5) T11(-5.5,0.5) T12(-4.5,0.5) T13(-3.5,0.5) T14(-2.5,0.5) T15(-1.5,0.5) T16(-0.5,0.5) T17(0.5,0.5) T18(1.5,0.5) T19(2.5,0.5) T20(3.5,0.5) T21(4.5,0.5) T22(5.5,0.5) T23(6.5,0.5) T24(7.5,0.5) T25(8.5,0.5) T26(9.5,0.5) T27(10.5,0.5) T28(11.5,0.5) T29(12.5,0.5) T30(13.5,0.5) T31(14.5,0.5) T32(15.5,0.5) U1(-15.5,-0.5) U2(-14.5,-0.5) U3(-13.5,-0.5) U4(-12.5,-0.5) U5(-11.5,-0.5) U6(-10.5,-0.5) U7(-9.5,-0.5) U8(-8.5,-0.5) U9(-7.5,-0.5) U10(-6.5,-0.5) U11(-5.5,-0.5) U12(-4.5,-0.5) U13(-3.5,-0.5) U14(-2.5,-0.5) U15(-1.5,-0.5) U16(-0.5,-0.5) U17(0.5,-0.5) U18(1.5,-0.5) U19(2.5,-0.5) U20(3.5,-0.5) U21(4.5,-0.5) U22(5.5,-0.5) U23(6.5,-0.5) U24(7.5,-0.5) U25(8.5,-0.5) U26(9.5,-0.5) U27(10.5,-0.5) U28(11.5,-0.5) U29(12.5,-0.5) U30(13.5,-0.5) U31(14.5,-0.5) U32(15.5,-0.5) V1(-15.5,-1.5) V2(-14.5,-1.5) V3(-13.5,-1.5) V4(-12.5,-1.5) V5(-11.5,-1.5) V6(-10.5,-1.5) V7(-9.5,-1.5) V8(-8.5,-1.5) V9(-7.5,-1.5) V10(-6.5,-1.5) V11(-5.5,-1.5) V12(-4.5,-1.5) V13(-3.5,-1.5) V14(-2.5,-1.5) V15(-1.5,-1.5) V16(-0.5,-1.5) V17(0.5,-1.5) V18(1.5,-1.5) V19(2.5,-1.5) V20(3.5,-1.5) V21(4.5,-1.5) V22(5.5,-1.5) V23(6.5,-1.5) V24(7.5,-1.5) V25(8.5,-1.5) V26(9.5,-1.5) V27(10.5,-1.5) V28(11.5,-1.5) V29(12.5,-1.5) V30(13.5,-1.5) V31(14.5,-1.5) V32(15.5,-1.5) W1(-15.5,-2.5) W2(-14.5,-2.5) W3(-13.5,-2.5) W4(-12.5,-2.5) W5(-11.5,-2.5) W6(-10.5,-2.5) W7(-9.5,-2.5) W8(-8.5,-2.5) W9(-7.5,-2.5) W10(-6.5,-2.5) W11(-5.5,-2.5) W12(-4.5,-2.5) W13(-3.5,-2.5) W14(-2.5,-2.5) W15(-1.5,-2.5) W16(-0.5,-2.5) W17(0.5,-2.5) W18(1.5,-2.5) W19(2.5,-2.5) W20(3.5,-2.5) W21(4.5,-2.5) W22(5.5,-2.5) W23(6.5,-2.5) W24(7.5,-2.5) W25(8.5,-2.5) W26(9.5,-2.5) W27(10.5,-2.5) W28(11.5,-2.5) W29(12.5,-2.5) W30(13.5,-2.5) W31(14.5,-2.5) W32(15.5,-2.5) Y1(-15.5,-3.5) Y2(-14.5,-3.5) Y3(-13.5,-3.5) Y4(-12.5,-3.5) Y5(-11.5,-3.5) Y6(-10.5,-3.5) Y7(-9.5,-3.5) Y8(-8.5,-3.5) Y9(-7.5,-3.5) Y10(-6.5,-3.5) Y11(-5.5,-3.5) Y12(-4.5,-3.5) Y13(-3.5,-3.5) Y14(-2.5,-3.5) Y15(-1.5,-3.5) Y16(-0.5,-3.5) Y17(0.5,-3.5) Y18(1.5,-3.5) Y19(2.5,-3.5) Y20(3.5,-3.5) Y21(4.5,-3.5) Y22(5.5,-3.5) Y23(6.5,-3.5) Y24(7.5,-3.5) Y25(8.5,-3.5) Y26(9.5,-3.5) Y27(10.5,-3.5) Y28(11.5,-3.5) Y29(12.5,-3.5) Y30(13.5,-3.5) Y31(14.5,-3.5) Y32(15.5,-3.5)
Top Overlay:
  circle w0.25: c-17.15,15.5 r0.125
  region: -15.5,16.5 -16.5,15.5 -16.5,16.5
  lines w0.2: -16.5,15.5 -15.5,16.5 ; -16.5,-16.5 -16.5,16.5 16.5,16.5 16.5,-16.5 -16.5,-16.5
Mechanical 13:
  lines w0.1: -16.5,-16.5 -16.5,16.5 16.5,16.5 16.5,-16.5 -16.5,-16.5
Mechanical 15:
  lines w0.1: -0.5,0 0.5,0 ; 0,-0.5 0,0.5 ; -17.5,-17.5 -17.5,17.5 17.5,17.5 17.5,-17.5 -17.5,-17.5
3D body: height 0, standoff 0, extent -16.5,-16.5 16.5,16.5

## BGA100P33X33-1089 [mm] "BGA, 1089-Leads, Body 35x35mm, Pitch 1mm"
height 3.5
pads (1089):
  round 0.5 smd: A1(-16,16) A2(-15,16) A3(-14,16) A4(-13,16) A5(-12,16) A6(-11,16) A7(-10,16) A8(-9,16) A9(-8,16) A10(-7,16) A11(-6,16) A12(-5,16) A13(-4,16) A14(-3,16) A15(-2,16) A16(-1,16) A17(0,16) A18(1,16) A19(2,16) A20(3,16) A21(4,16) A22(5,16) A23(6,16) A24(7,16) A25(8,16) A26(9,16) A27(10,16) A28(11,16) A29(12,16) A30(13,16) A31(14,16) A32(15,16) A33(16,16) AA1(-16,-4) AA2(-15,-4) AA3(-14,-4) AA4(-13,-4) AA5(-12,-4) AA6(-11,-4) AA7(-10,-4) AA8(-9,-4) AA9(-8,-4) AA10(-7,-4) AA11(-6,-4) AA12(-5,-4) AA13(-4,-4) AA14(-3,-4) AA15(-2,-4) AA16(-1,-4) AA17(0,-4) AA18(1,-4) AA19(2,-4) AA20(3,-4) AA21(4,-4) AA22(5,-4) AA23(6,-4) AA24(7,-4) AA25(8,-4) AA26(9,-4) AA27(10,-4) AA28(11,-4) AA29(12,-4) AA30(13,-4) AA31(14,-4) AA32(15,-4) AA33(16,-4) AB1(-16,-5) AB2(-15,-5) AB3(-14,-5) AB4(-13,-5) AB5(-12,-5) AB6(-11,-5) AB7(-10,-5) AB8(-9,-5) AB9(-8,-5) AB10(-7,-5) AB11(-6,-5) AB12(-5,-5) AB13(-4,-5) AB14(-3,-5) AB15(-2,-5) AB16(-1,-5) AB17(0,-5) AB18(1,-5) AB19(2,-5) AB20(3,-5) AB21(4,-5) AB22(5,-5) AB23(6,-5) AB24(7,-5) AB25(8,-5) AB26(9,-5) AB27(10,-5) AB28(11,-5) AB29(12,-5) AB30(13,-5) AB31(14,-5) AB32(15,-5) AB33(16,-5) AC1(-16,-6) AC2(-15,-6) AC3(-14,-6) AC4(-13,-6) AC5(-12,-6) AC6(-11,-6) AC7(-10,-6) AC8(-9,-6) AC9(-8,-6) AC10(-7,-6) AC11(-6,-6) AC12(-5,-6) AC13(-4,-6) AC14(-3,-6) AC15(-2,-6) AC16(-1,-6) AC17(0,-6) AC18(1,-6) AC19(2,-6) AC20(3,-6) AC21(4,-6) AC22(5,-6) AC23(6,-6) AC24(7,-6) AC25(8,-6) AC26(9,-6) AC27(10,-6) AC28(11,-6) AC29(12,-6) AC30(13,-6) AC31(14,-6) AC32(15,-6) AC33(16,-6) AD1(-16,-7) AD2(-15,-7) AD3(-14,-7) AD4(-13,-7) AD5(-12,-7) AD6(-11,-7) AD7(-10,-7) AD8(-9,-7) AD9(-8,-7) AD10(-7,-7) AD11(-6,-7) AD12(-5,-7) AD13(-4,-7) AD14(-3,-7) AD15(-2,-7) AD16(-1,-7) AD17(0,-7) AD18(1,-7) AD19(2,-7) AD20(3,-7) AD21(4,-7) AD22(5,-7) AD23(6,-7) AD24(7,-7) AD25(8,-7) AD26(9,-7) AD27(10,-7) AD28(11,-7) AD29(12,-7) AD30(13,-7) AD31(14,-7) AD32(15,-7) AD33(16,-7) AE1(-16,-8) AE2(-15,-8) AE3(-14,-8) AE4(-13,-8) AE5(-12,-8) AE6(-11,-8) AE7(-10,-8) AE8(-9,-8) AE9(-8,-8) AE10(-7,-8) AE11(-6,-8) AE12(-5,-8) AE13(-4,-8) AE14(-3,-8) AE15(-2,-8) AE16(-1,-8) AE17(0,-8) AE18(1,-8) AE19(2,-8) AE20(3,-8) AE21(4,-8) AE22(5,-8) AE23(6,-8) AE24(7,-8) AE25(8,-8) AE26(9,-8) AE27(10,-8) AE28(11,-8) AE29(12,-8) AE30(13,-8) AE31(14,-8) AE32(15,-8) AE33(16,-8) AF1(-16,-9) AF2(-15,-9) AF3(-14,-9) AF4(-13,-9) AF5(-12,-9) AF6(-11,-9) AF7(-10,-9) AF8(-9,-9) AF9(-8,-9) AF10(-7,-9) AF11(-6,-9) AF12(-5,-9) AF13(-4,-9) AF14(-3,-9) AF15(-2,-9) AF16(-1,-9) AF17(0,-9) AF18(1,-9) AF19(2,-9) AF20(3,-9) AF21(4,-9) AF22(5,-9) AF23(6,-9) AF24(7,-9) AF25(8,-9) AF26(9,-9) AF27(10,-9) AF28(11,-9) AF29(12,-9) AF30(13,-9) AF31(14,-9) AF32(15,-9) AF33(16,-9) AG1(-16,-10) AG2(-15,-10) AG3(-14,-10) AG4(-13,-10) AG5(-12,-10) AG6(-11,-10) AG7(-10,-10) AG8(-9,-10) AG9(-8,-10) AG10(-7,-10) AG11(-6,-10) AG12(-5,-10) AG13(-4,-10) AG14(-3,-10) AG15(-2,-10) AG16(-1,-10) AG17(0,-10) AG18(1,-10) AG19(2,-10) AG20(3,-10) AG21(4,-10) AG22(5,-10) AG23(6,-10) AG24(7,-10) AG25(8,-10) AG26(9,-10) AG27(10,-10) AG28(11,-10) AG29(12,-10) AG30(13,-10) AG31(14,-10) AG32(15,-10) AG33(16,-10) AH1(-16,-11) AH2(-15,-11) AH3(-14,-11) AH4(-13,-11) AH5(-12,-11) AH6(-11,-11) AH7(-10,-11) AH8(-9,-11) AH9(-8,-11) AH10(-7,-11) AH11(-6,-11) AH12(-5,-11) AH13(-4,-11) AH14(-3,-11) AH15(-2,-11) AH16(-1,-11) AH17(0,-11) AH18(1,-11) AH19(2,-11) AH20(3,-11) AH21(4,-11) AH22(5,-11) AH23(6,-11) AH24(7,-11) AH25(8,-11) AH26(9,-11) AH27(10,-11) AH28(11,-11) AH29(12,-11) AH30(13,-11) AH31(14,-11) AH32(15,-11) AH33(16,-11) AJ1(-16,-12) AJ2(-15,-12) AJ3(-14,-12) AJ4(-13,-12) AJ5(-12,-12) AJ6(-11,-12) AJ7(-10,-12) AJ8(-9,-12) AJ9(-8,-12) AJ10(-7,-12) AJ11(-6,-12) AJ12(-5,-12) AJ13(-4,-12) AJ14(-3,-12) AJ15(-2,-12) AJ16(-1,-12) AJ17(0,-12) AJ18(1,-12) AJ19(2,-12) AJ20(3,-12) AJ21(4,-12) AJ22(5,-12) AJ23(6,-12) AJ24(7,-12) AJ25(8,-12) AJ26(9,-12) AJ27(10,-12) AJ28(11,-12) AJ29(12,-12) AJ30(13,-12) AJ31(14,-12) AJ32(15,-12) AJ33(16,-12) AK1(-16,-13) AK2(-15,-13) AK3(-14,-13) AK4(-13,-13) AK5(-12,-13) AK6(-11,-13) AK7(-10,-13) AK8(-9,-13) AK9(-8,-13) AK10(-7,-13) AK11(-6,-13) AK12(-5,-13) AK13(-4,-13) AK14(-3,-13) AK15(-2,-13) AK16(-1,-13) AK17(0,-13) AK18(1,-13) AK19(2,-13) AK20(3,-13) AK21(4,-13) AK22(5,-13) AK23(6,-13) AK24(7,-13) AK25(8,-13) AK26(9,-13) AK27(10,-13) AK28(11,-13) AK29(12,-13) AK30(13,-13) AK31(14,-13) AK32(15,-13) AK33(16,-13) AL1(-16,-14) AL2(-15,-14) AL3(-14,-14) AL4(-13,-14) AL5(-12,-14) AL6(-11,-14) AL7(-10,-14) AL8(-9,-14) AL9(-8,-14) AL10(-7,-14) AL11(-6,-14) AL12(-5,-14) AL13(-4,-14) AL14(-3,-14) AL15(-2,-14) AL16(-1,-14) AL17(0,-14) AL18(1,-14) AL19(2,-14) AL20(3,-14) AL21(4,-14) AL22(5,-14) AL23(6,-14) AL24(7,-14) AL25(8,-14) AL26(9,-14) AL27(10,-14) AL28(11,-14) AL29(12,-14) AL30(13,-14) AL31(14,-14) AL32(15,-14) AL33(16,-14) AM1(-16,-15) AM2(-15,-15) AM3(-14,-15) AM4(-13,-15) AM5(-12,-15) AM6(-11,-15) AM7(-10,-15) AM8(-9,-15) AM9(-8,-15) AM10(-7,-15) AM11(-6,-15) AM12(-5,-15) AM13(-4,-15) AM14(-3,-15) AM15(-2,-15) AM16(-1,-15) AM17(0,-15) AM18(1,-15) AM19(2,-15) AM20(3,-15) AM21(4,-15) AM22(5,-15) AM23(6,-15) AM24(7,-15) AM25(8,-15) AM26(9,-15) AM27(10,-15) AM28(11,-15) AM29(12,-15) AM30(13,-15) AM31(14,-15) AM32(15,-15) AM33(16,-15) AN1(-16,-16) AN2(-15,-16) AN3(-14,-16) AN4(-13,-16) AN5(-12,-16) AN6(-11,-16) AN7(-10,-16) AN8(-9,-16) AN9(-8,-16) AN10(-7,-16) AN11(-6,-16) AN12(-5,-16) AN13(-4,-16) AN14(-3,-16) AN15(-2,-16) AN16(-1,-16) AN17(0,-16) AN18(1,-16) AN19(2,-16) AN20(3,-16) AN21(4,-16) AN22(5,-16) AN23(6,-16) AN24(7,-16) AN25(8,-16) AN26(9,-16) AN27(10,-16) AN28(11,-16) AN29(12,-16) AN30(13,-16) AN31(14,-16) AN32(15,-16) AN33(16,-16) B1(-16,15) B2(-15,15) B3(-14,15) B4(-13,15) B5(-12,15) B6(-11,15) B7(-10,15) B8(-9,15) B9(-8,15) B10(-7,15) B11(-6,15) B12(-5,15) B13(-4,15) B14(-3,15) B15(-2,15) B16(-1,15) B17(0,15) B18(1,15) B19(2,15) B20(3,15) B21(4,15) B22(5,15) B23(6,15) B24(7,15) B25(8,15) B26(9,15) B27(10,15) B28(11,15) B29(12,15) B30(13,15) B31(14,15) B32(15,15) B33(16,15) C1(-16,14) C2(-15,14) C3(-14,14) C4(-13,14) C5(-12,14) C6(-11,14) C7(-10,14) C8(-9,14) C9(-8,14) C10(-7,14) C11(-6,14) C12(-5,14) C13(-4,14) C14(-3,14) C15(-2,14) C16(-1,14) C17(0,14) C18(1,14) C19(2,14) C20(3,14) C21(4,14) C22(5,14) C23(6,14) C24(7,14) C25(8,14) C26(9,14) C27(10,14) C28(11,14) C29(12,14) C30(13,14) C31(14,14) C32(15,14) C33(16,14) D1(-16,13) D2(-15,13) D3(-14,13) D4(-13,13) D5(-12,13) D6(-11,13) D7(-10,13) D8(-9,13) D9(-8,13) D10(-7,13) D11(-6,13) D12(-5,13) D13(-4,13) D14(-3,13) D15(-2,13) D16(-1,13) D17(0,13) D18(1,13) D19(2,13) D20(3,13) D21(4,13) D22(5,13) D23(6,13) D24(7,13) D25(8,13) D26(9,13) D27(10,13) D28(11,13) D29(12,13) D30(13,13) D31(14,13) D32(15,13) D33(16,13) E1(-16,12) E2(-15,12) E3(-14,12) E4(-13,12) E5(-12,12) E6(-11,12) E7(-10,12) E8(-9,12) E9(-8,12) E10(-7,12) E11(-6,12) E12(-5,12) E13(-4,12) E14(-3,12) E15(-2,12) E16(-1,12) E17(0,12) E18(1,12) E19(2,12) E20(3,12) E21(4,12) E22(5,12) E23(6,12) E24(7,12) E25(8,12) E26(9,12) E27(10,12) E28(11,12) E29(12,12) E30(13,12) E31(14,12) E32(15,12) E33(16,12) F1(-16,11) F2(-15,11) F3(-14,11) F4(-13,11) F5(-12,11) F6(-11,11) F7(-10,11) F8(-9,11) F9(-8,11) F10(-7,11) F11(-6,11) F12(-5,11) F13(-4,11) F14(-3,11) F15(-2,11) F16(-1,11) F17(0,11) F18(1,11) F19(2,11) F20(3,11) F21(4,11) F22(5,11) F23(6,11) F24(7,11) F25(8,11) F26(9,11) F27(10,11) F28(11,11) F29(12,11) F30(13,11) F31(14,11) F32(15,11) F33(16,11) G1(-16,10) G2(-15,10) G3(-14,10) G4(-13,10) G5(-12,10) G6(-11,10) G7(-10,10) G8(-9,10) G9(-8,10) G10(-7,10) G11(-6,10) G12(-5,10) G13(-4,10) G14(-3,10) G15(-2,10) G16(-1,10) G17(0,10) G18(1,10) G19(2,10) G20(3,10) G21(4,10) G22(5,10) G23(6,10) G24(7,10) G25(8,10) G26(9,10) G27(10,10) G28(11,10) G29(12,10) G30(13,10) G31(14,10) G32(15,10) G33(16,10) H1(-16,9) H2(-15,9) H3(-14,9) H4(-13,9) H5(-12,9) H6(-11,9) H7(-10,9) H8(-9,9) H9(-8,9) H10(-7,9) H11(-6,9) H12(-5,9) H13(-4,9) H14(-3,9) H15(-2,9) H16(-1,9) H17(0,9) H18(1,9) H19(2,9) H20(3,9) H21(4,9) H22(5,9) H23(6,9) H24(7,9) H25(8,9) H26(9,9) H27(10,9) H28(11,9) H29(12,9) H30(13,9) H31(14,9) H32(15,9) H33(16,9) J1(-16,8) J2(-15,8) J3(-14,8) J4(-13,8) J5(-12,8) J6(-11,8) J7(-10,8) J8(-9,8) J9(-8,8) J10(-7,8) J11(-6,8) J12(-5,8) J13(-4,8) J14(-3,8) J15(-2,8) J16(-1,8) J17(0,8) J18(1,8) J19(2,8) J20(3,8) J21(4,8) J22(5,8) J23(6,8) J24(7,8) J25(8,8) J26(9,8) J27(10,8) J28(11,8) J29(12,8) J30(13,8) J31(14,8) J32(15,8) J33(16,8) K1(-16,7) K2(-15,7) K3(-14,7) K4(-13,7) K5(-12,7) K6(-11,7) K7(-10,7) K8(-9,7) K9(-8,7) K10(-7,7) K11(-6,7) K12(-5,7) K13(-4,7) K14(-3,7) K15(-2,7) K16(-1,7) K17(0,7) K18(1,7) K19(2,7) K20(3,7) K21(4,7) K22(5,7) K23(6,7) K24(7,7) K25(8,7) K26(9,7) K27(10,7) K28(11,7) K29(12,7) K30(13,7) K31(14,7) K32(15,7) K33(16,7) L1(-16,6) L2(-15,6) L3(-14,6) L4(-13,6) L5(-12,6) L6(-11,6) L7(-10,6) L8(-9,6) L9(-8,6) L10(-7,6) L11(-6,6) L12(-5,6) L13(-4,6) L14(-3,6) L15(-2,6) L16(-1,6) L17(0,6) L18(1,6) L19(2,6) L20(3,6) L21(4,6) L22(5,6) L23(6,6) L24(7,6) L25(8,6) L26(9,6) L27(10,6) L28(11,6) L29(12,6) L30(13,6) L31(14,6) L32(15,6) L33(16,6) M1(-16,5) M2(-15,5) M3(-14,5) M4(-13,5) M5(-12,5) M6(-11,5) M7(-10,5) M8(-9,5) M9(-8,5) M10(-7,5) M11(-6,5) M12(-5,5) M13(-4,5) M14(-3,5) M15(-2,5) M16(-1,5) M17(0,5) M18(1,5) M19(2,5) M20(3,5) M21(4,5) M22(5,5) M23(6,5) M24(7,5) M25(8,5) M26(9,5) M27(10,5) M28(11,5) M29(12,5) M30(13,5) M31(14,5) M32(15,5) M33(16,5) N1(-16,4) N2(-15,4) N3(-14,4) N4(-13,4) N5(-12,4) N6(-11,4) N7(-10,4) N8(-9,4) N9(-8,4) N10(-7,4) N11(-6,4) N12(-5,4) N13(-4,4) N14(-3,4) N15(-2,4) N16(-1,4) N17(0,4) N18(1,4) N19(2,4) N20(3,4) N21(4,4) N22(5,4) N23(6,4) N24(7,4) N25(8,4) N26(9,4) N27(10,4) N28(11,4) N29(12,4) N30(13,4) N31(14,4) N32(15,4) N33(16,4) P1(-16,3) P2(-15,3) P3(-14,3) P4(-13,3) P5(-12,3) P6(-11,3) P7(-10,3) P8(-9,3) P9(-8,3) P10(-7,3) P11(-6,3) P12(-5,3) P13(-4,3) P14(-3,3) P15(-2,3) P16(-1,3) P17(0,3) P18(1,3) P19(2,3) P20(3,3) P21(4,3) P22(5,3) P23(6,3) P24(7,3) P25(8,3) P26(9,3) P27(10,3) P28(11,3) P29(12,3) P30(13,3) P31(14,3) P32(15,3) P33(16,3) R1(-16,2) R2(-15,2) R3(-14,2) R4(-13,2) R5(-12,2) R6(-11,2) R7(-10,2) R8(-9,2) R9(-8,2) R10(-7,2) R11(-6,2) R12(-5,2) R13(-4,2) R14(-3,2) R15(-2,2) R16(-1,2) R17(0,2) R18(1,2) R19(2,2) R20(3,2) R21(4,2) R22(5,2) R23(6,2) R24(7,2) R25(8,2) R26(9,2) R27(10,2) R28(11,2) R29(12,2) R30(13,2) R31(14,2) R32(15,2) R33(16,2) T1(-16,1) T2(-15,1) T3(-14,1) T4(-13,1) T5(-12,1) T6(-11,1) T7(-10,1) T8(-9,1) T9(-8,1) T10(-7,1) T11(-6,1) T12(-5,1) T13(-4,1) T14(-3,1) T15(-2,1) T16(-1,1) T17(0,1) T18(1,1) T19(2,1) T20(3,1) T21(4,1) T22(5,1) T23(6,1) T24(7,1) T25(8,1) T26(9,1) T27(10,1) T28(11,1) T29(12,1) T30(13,1) T31(14,1) T32(15,1) T33(16,1) U1(-16,0) U2(-15,0) U3(-14,0) U4(-13,0) U5(-12,0) U6(-11,0) U7(-10,0) U8(-9,0) U9(-8,0) U10(-7,0) U11(-6,0) U12(-5,0) U13(-4,0) U14(-3,0) U15(-2,0) U16(-1,0) U17(0,0) U18(1,0) U19(2,0) U20(3,0) U21(4,0) U22(5,0) U23(6,0) U24(7,0) U25(8,0) U26(9,0) U27(10,0) U28(11,0) U29(12,0) U30(13,0) U31(14,0) U32(15,0) U33(16,0) V1(-16,-1) V2(-15,-1) V3(-14,-1) V4(-13,-1) V5(-12,-1) V6(-11,-1) V7(-10,-1) V8(-9,-1) V9(-8,-1) V10(-7,-1) V11(-6,-1) V12(-5,-1) V13(-4,-1) V14(-3,-1) V15(-2,-1) V16(-1,-1) V17(0,-1) V18(1,-1) V19(2,-1) V20(3,-1) V21(4,-1) V22(5,-1) V23(6,-1) V24(7,-1) V25(8,-1) V26(9,-1) V27(10,-1) V28(11,-1) V29(12,-1) V30(13,-1) V31(14,-1) V32(15,-1) V33(16,-1) W1(-16,-2) W2(-15,-2) W3(-14,-2) W4(-13,-2) W5(-12,-2) W6(-11,-2) W7(-10,-2) W8(-9,-2) W9(-8,-2) W10(-7,-2) W11(-6,-2) W12(-5,-2) W13(-4,-2) W14(-3,-2) W15(-2,-2) W16(-1,-2) W17(0,-2) W18(1,-2) W19(2,-2) W20(3,-2) W21(4,-2) W22(5,-2) W23(6,-2) W24(7,-2) W25(8,-2) W26(9,-2) W27(10,-2) W28(11,-2) W29(12,-2) W30(13,-2) W31(14,-2) W32(15,-2) W33(16,-2) Y1(-16,-3) Y2(-15,-3) Y3(-14,-3) Y4(-13,-3) Y5(-12,-3) Y6(-11,-3) Y7(-10,-3) Y8(-9,-3) Y9(-8,-3) Y10(-7,-3) Y11(-6,-3) Y12(-5,-3) Y13(-4,-3) Y14(-3,-3) Y15(-2,-3) Y16(-1,-3) Y17(0,-3) Y18(1,-3) Y19(2,-3) Y20(3,-3) Y21(4,-3) Y22(5,-3) Y23(6,-3) Y24(7,-3) Y25(8,-3) Y26(9,-3) Y27(10,-3) Y28(11,-3) Y29(12,-3) Y30(13,-3) Y31(14,-3) Y32(15,-3) Y33(16,-3)
Top Overlay:
  circle w0.25: c-18.15,16 r0.125
  region: -16.5,17.5 -17.5,16.5 -17.5,17.5
  lines w0.2: -17.5,16.5 -16.5,17.5 ; -17.5,-17.5 -17.5,17.5 17.5,17.5 17.5,-17.5 -17.5,-17.5
Mechanical 13:
  lines w0.1: -17.5,-17.5 -17.5,17.5 17.5,17.5 17.5,-17.5 -17.5,-17.5
Mechanical 15:
  lines w0.1: -0.5,0 0.5,0 ; 0,-0.5 0,0.5 ; -18.5,-18.5 -18.5,18.5 18.5,18.5 18.5,-18.5 -18.5,-18.5
3D body: height 0, standoff 0, extent -17.5,-17.5 17.5,17.5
